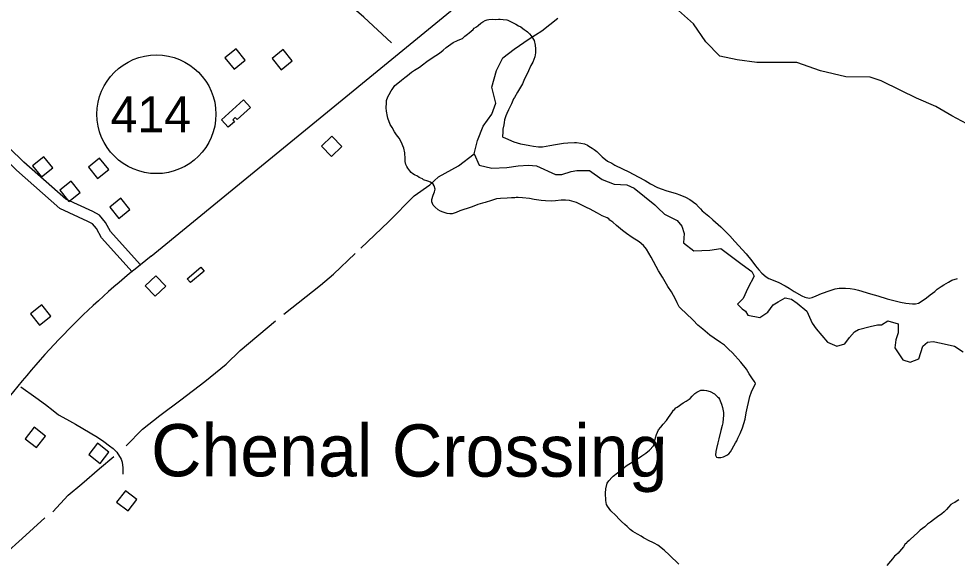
# Model space of a CAD drawing. Extents: x 3263578 to 3301413, y 764927 to 798602.
# Drawn here: x 3272360 to 3274964, y 776528 to 778038 of the extents above; entities that cross this region are included whole.
import ezdxf

# ---------------------------------------------------------------- set-up
doc = ezdxf.new("R2010")
doc.units = 0
for name, color, linetype in [('V-BLDG-OTLN', 7, 'Continuous'), ('V-ROAD-CNTR', 7, 'Continuous'), ('V-ROAD-IDEN', 7, 'Continuous'), ('V-SITE-VEGE', 7, 'Continuous'), ('V-TOPO-GNAM-IDEN', 7, 'Continuous'), ('V-TOPO-SHOR', 7, 'Continuous')]:
    doc.layers.add(name, color=color, linetype=linetype)

msp = doc.modelspace()

# ---------------------------------------------------------------- linework, layer by layer
at = {"layer": 'V-BLDG-OTLN'}
for points in [[(3272957.3, 777898.4), (3272988.4, 777923.5), (3272963.3, 777954.6), (3272932.1, 777929.5)], [(3273087.9, 777896.3), (3273119, 777921.4), (3273093.9, 777952.5), (3273062.8, 777927.4)], [(3273003, 777791.7), (3272965.7, 777758.1), (3272960.6, 777763.7), (3272953.8, 777757.6), (3272958.6, 777752.2), (3272941.2, 777736.6), (3272922.2, 777757.7), (3272983.7, 777813.1)], [(3273228.7, 777712.3), (3273199.9, 777684.5), (3273227.7, 777655.7), (3273256.5, 777683.5)], [(3272423.3, 777598.6), (3272454.4, 777623.7), (3272429.3, 777654.9), (3272398.2, 777629.8)], [(3272578.3, 777594.3), (3272609.4, 777619.4), (3272584.3, 777650.6), (3272553.2, 777625.5)], [(3272499.1, 777530.8), (3272530.2, 777555.9), (3272505.1, 777587), (3272474, 777561.9)], [(3272637.3, 777483.6), (3272668.5, 777508.7), (3272643.4, 777539.8), (3272612.2, 777514.7)], [(3272827.1, 777315.8), (3272865.4, 777348), (3272874.4, 777337.3), (3272836.1, 777305.1)], [(3272739.8, 777324), (3272711, 777296.2), (3272738.8, 777267.4), (3272767.6, 777295.2)], [(3272417.5, 777187.2), (3272448.6, 777212.4), (3272423.5, 777243.5), (3272392.4, 777218.4)], [(3272402.4, 776903.2), (3272377.9, 776871.6), (3272409.5, 776847.1), (3272434, 776878.7)], [(3272578.4, 776858.9), (3272553.9, 776827.3), (3272585.5, 776802.8), (3272610, 776834.4)], [(3272656, 776727), (3272631.5, 776695.4), (3272663.1, 776670.9), (3272687.6, 776702.5)]]:
    msp.add_lwpolyline(points, close=True, dxfattribs=at)
at = {"layer": 'V-ROAD-CNTR'}
for points in [[(3272674.5, 777335.2), (3272589.6, 777430), (3272575.7, 777455.2), (3272564.5, 777468.8), (3272551.9, 777475.4), (3272474, 777511.3), (3272353.2, 777617.4), (3272146.8, 777819.6), (3271837.3, 778083.6), (3271796.8, 778121.2), (3271770.2, 778148.5), (3271553.1, 778417.9), (3271529.2, 778444.5), (3271506.4, 778465.5), (3271436.4, 778518.6), (3271317.3, 778631.5), (3271166.3, 778763.1), (3270857.4, 779027.4), (3270685.7, 779179.7)], [(3272696.9, 777355.3), (3272614.2, 777447.5), (3272600.6, 777472.1), (3272583.8, 777492.6), (3272565.1, 777502.4), (3272490.5, 777536.7), (3272373.6, 777639.4), (3272167.1, 777841.8), (3271857.2, 778106), (3271817.8, 778142.7), (3271792.7, 778168.4), (3271575.9, 778437.4), (3271550.6, 778465.6), (3271525.7, 778488.5), (3271455.9, 778541.5), (3271337.4, 778653.7), (3271185.9, 778785.8), (3270877.1, 779050), (3270705.6, 779202.2)], [(3272727.6, 777378.3), (3272931.6, 777546.1), (3273669.8, 778151.7), (3274032.5, 778445.6), (3274277.5, 778649.5)], [(3272366, 777016), (3272407.4, 776986.4), (3272433.9, 776966.5), (3272455.4, 776949.7), (3272470, 776938.1), (3272492.5, 776926.2), (3272517, 776911.5), (3272558, 776888.1), (3272578.2, 776875.8), (3272595.8, 776863.7), (3272611.8, 776852.1), (3272621.6, 776844.3), (3272632.3, 776833.7), (3272643.8, 776814.5), (3272646.5, 776806.2), (3272649, 776790.6), (3272648.2, 776773)]]:
    msp.add_lwpolyline(points, dxfattribs=at)
msp.add_arc((3274100, 775597.4), 2248.3, 127.6198, 143.2639, dxfattribs=at)
at = {"layer": 'V-ROAD-IDEN'}
msp.add_circle((3272741.9, 777772.9), 165, dxfattribs=at)
at = {"layer": 'V-SITE-VEGE'}
for points in [[(3273380.8, 777781.2), (3273379.9, 777790.8), (3273380.1, 777804.2), (3273380.7, 777811.2), (3273384.1, 777821.3), (3273387.4, 777827.7), (3273393.4, 777838.3), (3273396.2, 777842), (3273403.8, 777852.6), (3273411.4, 777859.5), (3273422.3, 777867.3), (3273431.5, 777874.7), (3273438.5, 777881), (3273449.4, 777890), (3273458, 777895.7), (3273471.5, 777903.6), (3273480.2, 777909.9), (3273492.6, 777919.3), (3273501.9, 777926.1), (3273517.5, 777936.1), (3273527.8, 777942.9), (3273537.6, 777951.3), (3273546.2, 777958.2), (3273565.7, 777971.8), (3273577.6, 777978), (3273583.5, 777980.6), (3273591.1, 777983.7), (3273593.8, 777985.8), (3273597.6, 777990.1), (3273605.2, 777995.3), (3273610.1, 777999.5), (3273620.9, 778008.5), (3273623.6, 778011.6), (3273630.1, 778015.8), (3273634.5, 778019.5), (3273642.1, 778026.4), (3273647.5, 778030), (3273653.9, 778033.7), (3273659.3, 778035.2), (3273664.2, 778036.2), (3273674.3, 778036.6), (3273681.8, 778036.5), (3273691, 778037.4), (3273695.8, 778037.3), (3273704.3, 778036.1), (3273714.5, 778034.9), (3273717.2, 778034.4), (3273727.8, 778028.8), (3273738.9, 778022.8), (3273746.9, 778018.9), (3273752.8, 778015.6), (3273758.6, 778010.7), (3273762.3, 778008.5), (3273767.6, 778004.7), (3273771.8, 778001.9), (3273777.6, 777996), (3273781.9, 777991.1), (3273790.2, 777978.1), (3273793.2, 777964.7), (3273794.2, 777954.5), (3273794, 777943.2), (3273792.2, 777932), (3273786.7, 777917.6), (3273781.2, 777908.6), (3273774.5, 777893.2), (3273761.8, 777867.1), (3273757.4, 777857), (3273749.7, 777843.2), (3273744.2, 777834.2), (3273735.9, 777819.8), (3273733.2, 777815.6), (3273727.6, 777802.3), (3273719.4, 777785.3), (3273714.4, 777774.6), (3273711.6, 777768.3), (3273708.2, 777757.1), (3273706.5, 777750.1), (3273705.9, 777743.2), (3273703.6, 777731.4), (3273703.4, 777723.4), (3273702.7, 777711.1), (3273703.2, 777708.9), (3273708.6, 777707.8), (3273727.7, 777698.9), (3273734.1, 777696.2), (3273752.2, 777691.1), (3273763.5, 777689.3), (3273778.4, 777686.4), (3273788, 777684.6), (3273802.5, 777682.8), (3273813.7, 777682.7), (3273833.6, 777686.1), (3273849.1, 777688.6), (3273871.2, 777692.5), (3273884, 777693.9), (3273902.3, 777694.7), (3273908.1, 777694.6), (3273919.9, 777692.9), (3273929.5, 777691.1), (3273938.6, 777687.2), (3273942.3, 777684.5)], [(3274290, 777150.7), (3274277.8, 777159.5), (3274258.2, 777175.8), (3274244.5, 777186.8), (3274231.3, 777200.9), (3274211.2, 777220.5), (3274198, 777232.4), (3274192.2, 777237.9), (3274187, 777248.7), (3274182.3, 777259.4), (3274170.9, 777279.4), (3274161.4, 777294.6), (3274146.8, 777320), (3274135.3, 777337.8), (3274115, 777375.6), (3274102.4, 777397.7), (3274094, 777408.6), (3274081.3, 777418.9), (3274062.2, 777430.5), (3274046.3, 777441.4), (3274035.2, 777450.1), (3274018.3, 777464.3), (3274008.2, 777473), (3274000.3, 777479), (3273997.1, 777482.8), (3273992.9, 777485.6), (3273979, 777491.1), (3273965.7, 777497.8), (3273944, 777509.9), (3273937.1, 777513.2), (3273920.6, 777521.5), (3273907.3, 777527.6), (3273888.1, 777533.2), (3273876.8, 777534.4), (3273865.1, 777534.6), (3273849, 777532.7), (3273837.7, 777531.3), (3273821.6, 777532), (3273809.3, 777533.3), (3273790.1, 777536.3), (3273777.3, 777538.6), (3273758, 777541), (3273745.7, 777541.2), (3273740.4, 777541.8), (3273736.6, 777540.8), (3273727.5, 777540.4), (3273715.7, 777540), (3273696.4, 777538.7), (3273685.7, 777537.8), (3273671.7, 777533.2), (3273654.5, 777528.1), (3273646.4, 777525.5), (3273634, 777522), (3273627.6, 777519.4), (3273615.2, 777514.7), (3273606.6, 777511.7), (3273592.6, 777507), (3273584, 777504.5), (3273573.7, 777500.4), (3273568.3, 777497.8), (3273562.4, 777496.2), (3273556.5, 777495.8), (3273549.1, 777497), (3273537.3, 777500.9), (3273529.9, 777503.7), (3273524, 777507.5), (3273515.6, 777515.1), (3273510.3, 777520.6), (3273506.2, 777529.7), (3273506.3, 777536.2), (3273510.2, 777548.4), (3273513.5, 777557), (3273515.2, 777564.4), (3273512.7, 777574.1), (3273509.6, 777579), (3273502.1, 777584.4), (3273494.7, 777587.2), (3273483.5, 777591.1), (3273480.3, 777593.3), (3273471.3, 777597.2), (3273466, 777600.5), (3273458.5, 777604.4), (3273453.7, 777607.1), (3273448.4, 777610.9), (3273444.8, 777615.3), (3273439.5, 777622.9), (3273436.4, 777627.7), (3273434.3, 777633.1), (3273432.3, 777641.7), (3273432.4, 777649.2), (3273431, 777665.3), (3273428.6, 777678.7), (3273421.3, 777696.5), (3273415.1, 777706.8), (3273408.2, 777716), (3273402.5, 777724.1), (3273395.7, 777736), (3273391, 777744.6), (3273383.7, 777761.9), (3273382.7, 777766.7), (3273380.8, 777781.2)], [(3273942.3, 777684.5), (3273950.8, 777679), (3273957.1, 777674.6), (3273964, 777669.2), (3273973, 777659.9), (3273978.8, 777654.5), (3273994.1, 777642.5), (3274005.8, 777637), (3274013.8, 777631.5), (3274035.1, 777621), (3274053.1, 777612.7), (3274078.6, 777598.9), (3274097.8, 777588.5), (3274112.6, 777579.7), (3274132.3, 777569.2), (3274145.1, 777564.7), (3274155.7, 777560.8), (3274184, 777552.4), (3274194.7, 777549), (3274210.6, 777542.3), (3274222.3, 777535.7), (3274238.7, 777523.7), (3274246.7, 777516.1), (3274251.9, 777510.1), (3274256.7, 777504.2), (3274275.2, 777490), (3274286.3, 777479.6), (3274308, 777460), (3274332.8, 777435), (3274347, 777419.8), (3274378.1, 777385.1), (3274394.4, 777365.6), (3274404.9, 777351.5), (3274413.8, 777340.6), (3274422.3, 777331.4), (3274433.9, 777321.6), (3274441.9, 777316.7), (3274467.4, 777306.1), (3274486.6, 777296.7), (3274497.7, 777290.1), (3274512, 777280.3), (3274533.3, 777268.7), (3274541.8, 777264.8), (3274553.5, 777262), (3274562.1, 777263.5), (3274572.9, 777268.7), (3274588, 777274.9), (3274611.7, 777283.6), (3274625.7, 777288.2), (3274636.4, 777289.7), (3274648.2, 777290), (3274654.6, 777289.4), (3274666.9, 777289.2), (3274679.2, 777287.4), (3274689.9, 777284.6), (3274723.5, 777273.9), (3274743.8, 777268.3), (3274769.9, 777260.4), (3274807.2, 777250.7), (3274821.7, 777248.4), (3274839.8, 777246), (3274848.9, 777246.4), (3274857, 777248.4), (3274864.6, 777253.1), (3274878.6, 777263.1), (3274889.5, 777270.9), (3274902.5, 777280.9), (3274909, 777287.2), (3274919.3, 777294.1), (3274927.4, 777298.8), (3274939.8, 777306.6), (3274949.5, 777311.8), (3274964.6, 777316.4)], [(3274056.6, 776619.7), (3274048.2, 776627.8), (3274041.9, 776633.3), (3274032.9, 776642), (3274026.5, 776648), (3274017, 776658.3), (3274003.3, 776671.3), (3273993.3, 776684.4), (3273991.3, 776688.7), (3273988.7, 776700), (3273988, 776719.8), (3273989.2, 776732.6), (3273993.2, 776747.6), (3273997, 776754.5), (3274006.3, 776765), (3274009, 776767.7), (3274021.5, 776776.6), (3274030.7, 776783.9), (3274044.2, 776795), (3274048.6, 776797.6), (3274062.6, 776806.5), (3274082.1, 776819.1), (3274088.6, 776823.8), (3274100.5, 776831.7), (3274110.2, 776839.5), (3274121.1, 776852.2), (3274124.5, 776861.3), (3274126.8, 776874.1), (3274129.6, 776883.2), (3274135.7, 776895.9), (3274141.7, 776903.3), (3274148.3, 776911.8), (3274157.5, 776922.4), (3274163, 776930.3), (3274171.8, 776943.6), (3274176.7, 776950.5), (3274179.9, 776953.1), (3274183.2, 776957.4), (3274187.5, 776959.4), (3274203.8, 776971), (3274211.9, 776976.2), (3274222.7, 776983.6), (3274228.7, 776989.9), (3274236.3, 776997.3), (3274241.7, 777000.9), (3274248.7, 777004.6), (3274253, 777006.1), (3274262.1, 777006.5), (3274268.6, 777005.4), (3274278.7, 777003.1), (3274290.4, 776995.9), (3274294.6, 776992.7), (3274299.4, 776988.3), (3274302, 776985.6), (3274304.6, 776981.3), (3274306.2, 776977), (3274310.3, 776967.3), (3274312.8, 776958.1), (3274315.3, 776944.7), (3274315.7, 776935.6), (3274314.5, 776927.6), (3274313.8, 776915.3), (3274312.1, 776907.8), (3274308.1, 776893.9), (3274303, 776871.5), (3274299.6, 776860.3), (3274296.2, 776844.8), (3274294.4, 776836.3), (3274293.2, 776826.1), (3274295.3, 776822.3), (3274296.3, 776820.2), (3274300.1, 776819.1), (3274308.1, 776818.9), (3274315.6, 776821), (3274324.8, 776825.7), (3274330.2, 776829.9), (3274335.1, 776835.1), (3274339, 776841.5), (3274344.5, 776852.1), (3274348.9, 776860.1), (3274352.7, 776865.9), (3274355, 776872.9), (3274361.6, 776886.2), (3274368.2, 776901.6), (3274375.6, 776925.6), (3274379, 776943.8), (3274388.8, 776988.6), (3274393.3, 777001.9), (3274399.9, 777015.7), (3274404.9, 777023.7), (3274403.8, 777027.5), (3274400.7, 777031.8), (3274396, 777038.3), (3274387.1, 777051.8), (3274379.2, 777064.3), (3274363.5, 777084.3), (3274340.8, 777109.8), (3274329.7, 777120.7), (3274318.1, 777131), (3274307, 777139.2), (3274290, 777150.7)], [(3274968.4, 776702), (3274961.8, 776696.8), (3274958.1, 776694.7), (3274952.7, 776692.1), (3274946.2, 776688.4), (3274940.2, 776681), (3274934.7, 776675.2)], [(3274934.7, 776675.2), (3274927.7, 776668.4), (3274921.2, 776662.6), (3274909.8, 776654.7), (3274898.4, 776646.3), (3274889.8, 776639.5), (3274882.2, 776633.7), (3274874, 776626.9), (3274861.6, 776617.4), (3274854, 776610.5), (3274835, 776592.1), (3274831.2, 776588.9), (3274825.7, 776584.2), (3274824.1, 776582.6), (3274819.2, 776577.3), (3274815.4, 776571.5), (3274809.4, 776564.6), (3274804.5, 776558.3), (3274800.7, 776554), (3274794.2, 776548.2), (3274790.4, 776545.6), (3274787.1, 776541.9), (3274784.4, 776538.2), (3274778.9, 776531.3), (3274769.1, 776519.1)], [(3274191.3, 776523.4), (3274165.4, 776548.4), (3274151.1, 776561.5), (3274133.1, 776575.7), (3274123.6, 776581.2), (3274105.5, 776590), (3274099.6, 776593.3), (3274093.8, 776596.1), (3274086.9, 776600.5), (3274077.3, 776606), (3274064.1, 776614.2), (3274056.6, 776619.7)]]:
    msp.add_lwpolyline(points, dxfattribs=at)
at = {"layer": 'V-TOPO-SHOR'}
for points in [[(3273394.6, 777971.7), (3273317.3, 778042.3), (3273244.5, 778106.3), (3273151.8, 778185.8)], [(3274722.9, 777875.8), (3274655.6, 777877.2), (3274584.9, 777893.3), (3274518.9, 777916.8), (3274469.6, 777917), (3274408.1, 777916.3), (3274353.7, 777924.1), (3274305.8, 777934.7), (3274266.4, 777974.2), (3274232.4, 778024.4), (3274190.9, 778061)], [(3273457.3, 777546.6), (3273500.5, 777576.7), (3273524.7, 777598.7), (3273579.9, 777629.6), (3273624, 777662.7), (3273632.9, 777700.2), (3273648.3, 777740), (3273672.6, 777773.1), (3273683.6, 777804), (3273672.6, 777848.1), (3273685.9, 777894.4), (3273703.5, 777929.8), (3273734.4, 777954), (3273776.3, 777982.7), (3273811.7, 778004.8), (3273855.8, 778040.1)], [(3275004.9, 777738.5), (3274949.2, 777768.3), (3274904.8, 777794.4), (3274851.7, 777818), (3274808.1, 777838.8), (3274753.2, 777866), (3274722.9, 777875.8)], [(3273624, 777662.7), (3273637.3, 777631.8), (3273672.6, 777623), (3273714.5, 777625.2), (3273745.4, 777629.6), (3273774.1, 777631.8), (3273796.2, 777629.6), (3273849.1, 777605.3), (3273866.8, 777605.3), (3273893.3, 777614.2), (3273908.7, 777616.4), (3273944, 777616.4), (3273979.3, 777592.1), (3274012.4, 777578.8), (3274047.8, 777576.6), (3274067.6, 777567.8), (3274125, 777521.4), (3274133.8, 777512.6), (3274151.5, 777495), (3274186.8, 777477.3), (3274200, 777461.9), (3274206.6, 777442), (3274204.4, 777415.5), (3274233.1, 777393.4), (3274277.3, 777395.6), (3274308.2, 777400.1), (3274367.7, 777355.9), (3274394.2, 777336), (3274400.8, 777322.8), (3274383.2, 777289.7), (3274369.9, 777261), (3274354.5, 777245.6), (3274367.7, 777232.3), (3274376.6, 777225.7), (3274383.2, 777214.7), (3274416.3, 777208), (3274438.3, 777223.5), (3274453.8, 777243.3), (3274467, 777252.2), (3274486.9, 777263.2), (3274504.6, 777258.8), (3274520, 777247.8), (3274546.5, 777225.7), (3274561.9, 777192.6), (3274573, 777177.1), (3274603.9, 777139.6), (3274630.3, 777128.6), (3274652.4, 777135.2), (3274665.7, 777152.8), (3274678.9, 777168.3), (3274689.9, 777174.9), (3274723, 777183.7), (3274742.9, 777188.1), (3274753.9, 777188.1), (3274771.6, 777199.2), (3274800.3, 777190.4), (3274800.3, 777166.1), (3274793.7, 777146.2), (3274791.4, 777124.1), (3274813.5, 777091), (3274833.4, 777084.4), (3274857.6, 777093.2), (3274868.7, 777128.6), (3274881.9, 777139.6), (3274897.4, 777141.8), (3274919.4, 777137.4), (3274957, 777128.5), (3274981.2, 777113.1)], [(3273309.1, 777401.3), (3273385.9, 777473.8), (3273457.3, 777546.6)], [(3273095, 777217.5), (3273197.6, 777298.5), (3273233.4, 777328.3), (3273293, 777386)], [(3272658.1, 776852.2), (3272702.8, 776898.2), (3272750.9, 776935.7), (3272809.8, 776979.9), (3272875.9, 777030.1), (3272935.7, 777078.6), (3272974.2, 777116.9), (3273072.1, 777199)], [(3272454, 776668.6), (3272497.2, 776715), (3272534.8, 776746.4), (3272583.6, 776788.9), (3272624.1, 776821.7)], [(3272238.4, 776467), (3272281.1, 776512.2), (3272322.5, 776552), (3272369.6, 776594.5), (3272432.5, 776652.1)]]:
    msp.add_lwpolyline(points, dxfattribs=at)

# ---------------------------------------------------------------- texts
at = {"layer": 'V-ROAD-IDEN'}
msp.add_text('414', height=100, rotation=359.9292, dxfattribs=at).set_placement((3272614.7, 777723))
at = {"layer": 'V-TOPO-GNAM-IDEN'}
msp.add_text('Chenal Crossing', height=145, rotation=359.9292, dxfattribs=at).set_placement((3272726.8, 776767.2))

doc.saveas('drawing.dxf')
